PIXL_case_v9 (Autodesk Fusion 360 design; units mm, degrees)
part number: 0.96Oled_W_4_Buttons
base_feature "Base Feature"
work_plane "WorkPlane1" AlongDistance -6.5 ExtraOffset 0
sketch "Sketch1" plane through (0, 0, -6.5) normal (0, 0, 1) x axis (1, 0, 0)
  line L1 (24.2, -27.5) -> (-24.2, -27.5)
  line L2 (24.2, 15.7) -> (24.2, -27.5)
  line L3 (-24.2, 15.7) -> (24.2, 15.7)
  line L4 (-24.2, -27.5) -> (-24.2, 15.7)
extrude "Extrude1" new body sketch "Sketch1" along normal blind 11.8
fillet "Fillet1" radius 5
fillet "Fillet2" radius 1.4
work_plane "WorkPlane2" AlongDistance -6.5 ExtraOffset 0
sketch "Sketch2" plane through (0, 0, -6.5) normal (0, 0, 1) x axis (1, 0, 0)
  line L1 (22.2, -25.5) -> (-22.2, -25.5)
  line L2 (22.2, 13.7) -> (22.2, -25.5)
  line L3 (-22.2, 13.7) -> (22.2, 13.7)
  line L4 (-22.2, -25.5) -> (-22.2, 13.7)
extrude "Extrude2" cut sketch "Sketch2" along normal blind 9.3
fillet "Fillet3" radius 1.7
work_plane "WorkPlane3" AlongDistance 2.79 ExtraOffset 0
sketch "Sketch3" plane through (0, 0, 2.79) normal (0, 0, 1) x axis (1, 0, 0)
  line L1 (20.7, -11.3) -> (11, -11.3)
  line L2 (20.7, 11.7) -> (20.7, -11.3)
  line L3 (11, 11.7) -> (20.7, 11.7)
  line L4 (11, -11.3) -> (11, 11.7)
extrude "Extrude3" cut sketch "Sketch3" along normal blind 1.56
work_plane "WorkPlane4" AlongDistance 2.79 ExtraOffset 0
sketch "Sketch4" plane through (0, 0, 2.79) normal (0, 0, 1) x axis (1, 0, 0)
  line L1 (10, 9.6) -> (-10.8, 9.6)
  line L2 (10, 12.2) -> (10, 9.6)
  line L3 (-10.8, 12.2) -> (10, 12.2)
  line L4 (-10.8, 9.6) -> (-10.8, 12.2)
extrude "Extrude4" cut sketch "Sketch4" along normal blind 0.91
work_plane "WorkPlane5" AlongDistance 4.34 ExtraOffset 0
sketch "Sketch5" plane through (0, 0, 4.34) normal (0, 0, 1) x axis (1, 0, 0)
  line L1 (12.1, 5.6) -> (11.5, 5.6)
  line L2 (12.1, 11.8) -> (12.1, 5.6)
  line L3 (11.5, 11.8) -> (12.1, 11.8)
  line L4 (11.5, 5.6) -> (11.5, 11.8)
extrude "Extrude5" cut sketch "Sketch5" along normal blind 1.06
work_plane "WorkPlane6" AlongDistance 4.34 ExtraOffset 0
sketch "Sketch6" plane through (0, 0, 4.34) normal (0, 0, 1) x axis (1, 0, 0)
  line L1 (19.6, 11.2) -> (11.5, 11.2)
  line L2 (19.6, 11.8) -> (19.6, 11.2)
  line L3 (11.5, 11.8) -> (19.6, 11.8)
  line L4 (11.5, 11.2) -> (11.5, 11.8)
extrude "Extrude6" cut sketch "Sketch6" along normal blind 1.06
work_plane "WorkPlane7" AlongDistance 4.34 ExtraOffset 0
sketch "Sketch7" plane through (0, 0, 4.34) normal (0, 0, 1) x axis (1, 0, 0)
  line L1 (19.6, 5.6) -> (11.5, 5.6)
  line L2 (19.6, 6.2) -> (19.6, 5.6)
  line L3 (11.5, 6.2) -> (19.6, 6.2)
  line L4 (11.5, 5.6) -> (11.5, 6.2)
extrude "Extrude7" cut sketch "Sketch7" along normal blind 1.06
work_plane "WorkPlane8" AlongDistance 4.34 ExtraOffset 0
sketch "Sketch8" plane through (0, 0, 4.34) normal (0, 0, 1) x axis (1, 0, 0)
  line L1 (12.1, -0.07) -> (11.5, -0.07)
  line L2 (12.1, 6.13) -> (12.1, -0.07)
  line L3 (11.5, 6.13) -> (12.1, 6.13)
  line L4 (11.5, -0.07) -> (11.5, 6.13)
extrude "Extrude8" cut sketch "Sketch8" along normal blind 1.06
work_plane "WorkPlane9" AlongDistance 4.34 ExtraOffset 0
sketch "Sketch9" plane through (0, 0, 4.34) normal (0, 0, 1) x axis (1, 0, 0)
  line L1 (19.6, 5.53) -> (11.5, 5.53)
  line L2 (19.6, 6.13) -> (19.6, 5.53)
  line L3 (11.5, 6.13) -> (19.6, 6.13)
  line L4 (11.5, 5.53) -> (11.5, 6.13)
extrude "Extrude9" cut sketch "Sketch9" along normal blind 1.06
work_plane "WorkPlane10" AlongDistance 4.34 ExtraOffset 0
sketch "Sketch10" plane through (0, 0, 4.34) normal (0, 0, 1) x axis (1, 0, 0)
  line L1 (19.6, -0.07) -> (11.5, -0.07)
  line L2 (19.6, 0.53) -> (19.6, -0.07)
  line L3 (11.5, 0.53) -> (19.6, 0.53)
  line L4 (11.5, -0.07) -> (11.5, 0.53)
extrude "Extrude10" cut sketch "Sketch10" along normal blind 1.06
work_plane "WorkPlane11" AlongDistance 4.34 ExtraOffset 0
sketch "Sketch11" plane through (0, 0, 4.34) normal (0, 0, 1) x axis (1, 0, 0)
  line L1 (12.1, -5.73) -> (11.5, -5.73)
  line L2 (12.1, 0.47) -> (12.1, -5.73)
  line L3 (11.5, 0.47) -> (12.1, 0.47)
  line L4 (11.5, -5.73) -> (11.5, 0.47)
extrude "Extrude11" cut sketch "Sketch11" along normal blind 1.06
work_plane "WorkPlane12" AlongDistance 4.34 ExtraOffset 0
sketch "Sketch12" plane through (0, 0, 4.34) normal (0, 0, 1) x axis (1, 0, 0)
  line L1 (19.6, -0.13) -> (11.5, -0.13)
  line L2 (19.6, 0.47) -> (19.6, -0.13)
  line L3 (11.5, 0.47) -> (19.6, 0.47)
  line L4 (11.5, -0.13) -> (11.5, 0.47)
extrude "Extrude12" cut sketch "Sketch12" along normal blind 1.06
work_plane "WorkPlane13" AlongDistance 4.34 ExtraOffset 0
sketch "Sketch13" plane through (0, 0, 4.34) normal (0, 0, 1) x axis (1, 0, 0)
  line L1 (19.6, -5.73) -> (11.5, -5.73)
  line L2 (19.6, -5.13) -> (19.6, -5.73)
  line L3 (11.5, -5.13) -> (19.6, -5.13)
  line L4 (11.5, -5.73) -> (11.5, -5.13)
extrude "Extrude13" cut sketch "Sketch13" along normal blind 1.06
work_plane "WorkPlane14" AlongDistance 4.34 ExtraOffset 0
sketch "Sketch14" plane through (0, 0, 4.34) normal (0, 0, 1) x axis (1, 0, 0)
  line L1 (12.1, -11.4) -> (11.5, -11.4)
  line L2 (12.1, -5.2) -> (12.1, -11.4)
  line L3 (11.5, -5.2) -> (12.1, -5.2)
  line L4 (11.5, -11.4) -> (11.5, -5.2)
extrude "Extrude14" cut sketch "Sketch14" along normal blind 1.06
work_plane "WorkPlane15" AlongDistance 4.34 ExtraOffset 0
sketch "Sketch15" plane through (0, 0, 4.34) normal (0, 0, 1) x axis (1, 0, 0)
  line L1 (19.6, -5.8) -> (11.5, -5.8)
  line L2 (19.6, -5.2) -> (19.6, -5.8)
  line L3 (11.5, -5.2) -> (19.6, -5.2)
  line L4 (11.5, -5.8) -> (11.5, -5.2)
extrude "Extrude15" cut sketch "Sketch15" along normal blind 1.06
work_plane "WorkPlane16" AlongDistance 4.34 ExtraOffset 0
sketch "Sketch16" plane through (0, 0, 4.34) normal (0, 0, 1) x axis (1, 0, 0)
  line L1 (19.6, -11.4) -> (11.5, -11.4)
  line L2 (19.6, -10.8) -> (19.6, -11.4)
  line L3 (11.5, -10.8) -> (19.6, -10.8)
  line L4 (11.5, -11.4) -> (11.5, -10.8)
extrude "Extrude16" cut sketch "Sketch16" along normal blind 1.06
work_plane "WorkPlane17" AlongDistance 4.34 ExtraOffset 0
sketch "Sketch17" plane through (0, 0, 4.34) normal (0, 0, 1) x axis (1, 0, 0)
  line L1 (20.7, 6.2) -> (18.4, 6.2)
  line L2 (20.7, 11.2) -> (20.7, 6.2)
  line L3 (18.4, 11.2) -> (20.7, 11.2)
  line L4 (18.4, 6.2) -> (18.4, 11.2)
extrude "Extrude17" cut sketch "Sketch17" along normal blind 0.46
work_plane "WorkPlane18" AlongDistance 4.34 ExtraOffset 0
sketch "Sketch18" plane through (0, 0, 4.34) normal (0, 0, 1) x axis (1, 0, 0)
  line L1 (20.7, 0.53) -> (18.4, 0.53)
  line L2 (20.7, 5.53) -> (20.7, 0.53)
  line L3 (18.4, 5.53) -> (20.7, 5.53)
  line L4 (18.4, 0.53) -> (18.4, 5.53)
extrude "Extrude18" cut sketch "Sketch18" along normal blind 0.46
work_plane "WorkPlane19" AlongDistance 4.34 ExtraOffset 0
sketch "Sketch19" plane through (0, 0, 4.34) normal (0, 0, 1) x axis (1, 0, 0)
  line L1 (20.7, -5.13) -> (18.4, -5.13)
  line L2 (20.7, -0.13) -> (20.7, -5.13)
  line L3 (18.4, -0.13) -> (20.7, -0.13)
  line L4 (18.4, -5.13) -> (18.4, -0.13)
extrude "Extrude19" cut sketch "Sketch19" along normal blind 0.46
work_plane "WorkPlane20" AlongDistance 4.34 ExtraOffset 0
sketch "Sketch20" plane through (0, 0, 4.34) normal (0, 0, 1) x axis (1, 0, 0)
  line L1 (20.7, -10.8) -> (18.4, -10.8)
  line L2 (20.7, -5.8) -> (20.7, -10.8)
  line L3 (18.4, -5.8) -> (20.7, -5.8)
  line L4 (18.4, -10.8) -> (18.4, -5.8)
extrude "Extrude20" cut sketch "Sketch20" along normal blind 0.46
work_plane "WorkPlane21" AlongDistance 2.79 ExtraOffset 0
sketch "Sketch21" plane through (0, 0, 2.79) normal (0, 0, 1) x axis (1, 0, 0)
  line L1 (7, -6.6) -> (-16.3, -6.6)
  line L2 (7, 6.4) -> (7, -6.6)
  line L3 (-16.3, 6.4) -> (7, 6.4)
  line L4 (-16.3, -6.6) -> (-16.3, 6.4)
extrude "Extrude21" cut sketch "Sketch21" along normal blind 2.61
chamfer "Chamfer1" distance 1.2
work_plane "WorkPlane22" AlongDistance 1.6 ExtraOffset 0
sketch "Sketch22" plane through (0, 0, 1.6) normal (0, 0, 1) x axis (1, 0, 0)
  circle C1 centre (-20.5, -12) radius 1.5
extrude "Extrude22" add sketch "Sketch22" along normal blind 1.21
work_plane "WorkPlane23" AlongDistance 1.6 ExtraOffset 0
sketch "Sketch23" plane through (0, 0, 1.6) normal (0, 0, 1) x axis (1, 0, 0)
  circle C1 centre (-20.5, 12) radius 1.5
extrude "Extrude23" add sketch "Sketch23" along normal blind 1.21
work_plane "WorkPlane24" AlongDistance 1.6 ExtraOffset 0
sketch "Sketch24" plane through (0, 0, 1.6) normal (0, 0, 1) x axis (1, 0, 0)
  circle C1 centre (20.5, -12) radius 1.5
extrude "Extrude24" add sketch "Sketch24" along normal blind 1.21
work_plane "WorkPlane25" AlongDistance 1.6 ExtraOffset 0
sketch "Sketch25" plane through (0, 0, 1.6) normal (0, 0, 1) x axis (1, 0, 0)
  circle C1 centre (20.5, 12) radius 1.5
extrude "Extrude25" add sketch "Sketch25" along normal blind 1.21
work_plane "WorkPlane26" AlongDistance 5.3 ExtraOffset 0
sketch "Sketch26" plane through (0, 0, 5.3) normal (0, 0, 1) x axis (1, 0, 0)
  line L1 (-16.5, -17.8) -> (-19.8, -17.8)
  line L2 (-16.5, -16.7) -> (-16.5, -17.8)
  line L3 (-19.8, -16.7) -> (-16.5, -16.7)
  line L4 (-19.8, -17.8) -> (-19.8, -16.7)
  line L5 (-18.7, -18.9) -> (-19.8, -18.9)
  line L6 (-18.7, -17.8) -> (-18.7, -18.9)
  line L7 (-19.8, -17.8) -> (-18.7, -17.8)
  line L8 (-19.8, -18.9) -> (-19.8, -17.8)
  line L9 (-15.4, -18.9) -> (-16.5, -18.9)
  line L10 (-15.4, -17.8) -> (-15.4, -18.9)
  line L11 (-16.5, -17.8) -> (-15.4, -17.8)
  line L12 (-16.5, -18.9) -> (-16.5, -17.8)
  line L13 (-18.7, -20) -> (-19.8, -20)
  line L14 (-18.7, -18.9) -> (-18.7, -20)
  line L15 (-19.8, -18.9) -> (-18.7, -18.9)
  line L16 (-19.8, -20) -> (-19.8, -18.9)
  line L17 (-15.4, -20) -> (-16.5, -20)
  line L18 (-15.4, -18.9) -> (-15.4, -20)
  line L19 (-16.5, -18.9) -> (-15.4, -18.9)
  line L20 (-16.5, -20) -> (-16.5, -18.9)
  line L21 (-16.5, -21.1) -> (-19.8, -21.1)
  line L22 (-16.5, -20) -> (-16.5, -21.1)
  line L23 (-19.8, -20) -> (-16.5, -20)
  line L24 (-19.8, -21.1) -> (-19.8, -20)
  line L25 (-18.7, -22.2) -> (-19.8, -22.2)
  line L26 (-18.7, -21.1) -> (-18.7, -22.2)
  line L27 (-19.8, -21.1) -> (-18.7, -21.1)
  line L28 (-19.8, -22.2) -> (-19.8, -21.1)
  line L29 (-18.7, -23.3) -> (-19.8, -23.3)
  line L30 (-18.7, -22.2) -> (-18.7, -23.3)
  line L31 (-19.8, -22.2) -> (-18.7, -22.2)
  line L32 (-19.8, -23.3) -> (-19.8, -22.2)
  line L33 (-13.2, -17.8) -> (-14.3, -17.8)
  line L34 (-13.2, -16.7) -> (-13.2, -17.8)
  line L35 (-14.3, -16.7) -> (-13.2, -16.7)
  line L36 (-14.3, -17.8) -> (-14.3, -16.7)
  line L37 (-13.2, -20) -> (-14.3, -20)
  line L38 (-13.2, -18.9) -> (-13.2, -20)
  line L39 (-14.3, -18.9) -> (-13.2, -18.9)
  line L40 (-14.3, -20) -> (-14.3, -18.9)
  line L41 (-13.2, -21.1) -> (-14.3, -21.1)
  line L42 (-13.2, -20) -> (-13.2, -21.1)
  line L43 (-14.3, -20) -> (-13.2, -20)
  line L44 (-14.3, -21.1) -> (-14.3, -20)
  line L45 (-13.2, -22.2) -> (-14.3, -22.2)
  line L46 (-13.2, -21.1) -> (-13.2, -22.2)
  line L47 (-14.3, -21.1) -> (-13.2, -21.1)
  line L48 (-14.3, -22.2) -> (-14.3, -21.1)
  line L49 (-13.2, -23.3) -> (-14.3, -23.3)
  line L50 (-13.2, -22.2) -> (-13.2, -23.3)
  line L51 (-14.3, -22.2) -> (-13.2, -22.2)
  line L52 (-14.3, -23.3) -> (-14.3, -22.2)
  line L53 (-11, -17.8) -> (-12.1, -17.8)
  line L54 (-11, -16.7) -> (-11, -17.8)
  line L55 (-12.1, -16.7) -> (-11, -16.7)
  line L56 (-12.1, -17.8) -> (-12.1, -16.7)
  line L57 (-7.7, -17.8) -> (-8.8, -17.8)
  line L58 (-7.7, -16.7) -> (-7.7, -17.8)
  line L59 (-8.8, -16.7) -> (-7.7, -16.7)
  line L60 (-8.8, -17.8) -> (-8.8, -16.7)
  line L61 (-11, -18.9) -> (-12.1, -18.9)
  line L62 (-11, -17.8) -> (-11, -18.9)
  line L63 (-12.1, -17.8) -> (-11, -17.8)
  line L64 (-12.1, -18.9) -> (-12.1, -17.8)
  line L65 (-7.7, -18.9) -> (-8.8, -18.9)
  line L66 (-7.7, -17.8) -> (-7.7, -18.9)
  line L67 (-8.8, -17.8) -> (-7.7, -17.8)
  line L68 (-8.8, -18.9) -> (-8.8, -17.8)
  line L69 (-8.8, -20) -> (-11, -20)
  line L70 (-8.8, -18.9) -> (-8.8, -20)
  line L71 (-11, -18.9) -> (-8.8, -18.9)
  line L72 (-11, -20) -> (-11, -18.9)
  line L73 (-8.8, -21.1) -> (-11, -21.1)
  line L74 (-8.8, -20) -> (-8.8, -21.1)
  line L75 (-11, -20) -> (-8.8, -20)
  line L76 (-11, -21.1) -> (-11, -20)
  line L77 (-11, -22.2) -> (-12.1, -22.2)
  line L78 (-11, -21.1) -> (-11, -22.2)
  line L79 (-12.1, -21.1) -> (-11, -21.1)
  line L80 (-12.1, -22.2) -> (-12.1, -21.1)
  line L81 (-7.7, -22.2) -> (-8.8, -22.2)
  line L82 (-7.7, -21.1) -> (-7.7, -22.2)
  line L83 (-8.8, -21.1) -> (-7.7, -21.1)
  line L84 (-8.8, -22.2) -> (-8.8, -21.1)
  line L85 (-11, -23.3) -> (-12.1, -23.3)
  line L86 (-11, -22.2) -> (-11, -23.3)
  line L87 (-12.1, -22.2) -> (-11, -22.2)
  line L88 (-12.1, -23.3) -> (-12.1, -22.2)
  line L89 (-7.7, -23.3) -> (-8.8, -23.3)
  line L90 (-7.7, -22.2) -> (-7.7, -23.3)
  line L91 (-8.8, -22.2) -> (-7.7, -22.2)
  line L92 (-8.8, -23.3) -> (-8.8, -22.2)
  line L93 (-5.5, -17.8) -> (-6.6, -17.8)
  line L94 (-5.5, -16.7) -> (-5.5, -17.8)
  line L95 (-6.6, -16.7) -> (-5.5, -16.7)
  line L96 (-6.6, -17.8) -> (-6.6, -16.7)
  line L97 (-5.5, -18.9) -> (-6.6, -18.9)
  line L98 (-5.5, -17.8) -> (-5.5, -18.9)
  line L99 (-6.6, -17.8) -> (-5.5, -17.8)
  line L100 (-6.6, -18.9) -> (-6.6, -17.8)
  line L101 (-5.5, -20) -> (-6.6, -20)
  line L102 (-5.5, -18.9) -> (-5.5, -20)
  line L103 (-6.6, -18.9) -> (-5.5, -18.9)
  line L104 (-6.6, -20) -> (-6.6, -18.9)
  line L105 (-5.5, -21.1) -> (-6.6, -21.1)
  line L106 (-5.5, -20) -> (-5.5, -21.1)
  line L107 (-6.6, -20) -> (-5.5, -20)
  line L108 (-6.6, -21.1) -> (-6.6, -20)
  line L109 (-5.5, -22.2) -> (-6.6, -22.2)
  line L110 (-5.5, -21.1) -> (-5.5, -22.2)
  line L111 (-6.6, -21.1) -> (-5.5, -21.1)
  line L112 (-6.6, -22.2) -> (-6.6, -21.1)
  line L113 (-2.2, -23.3) -> (-6.6, -23.3)
  line L114 (-2.2, -22.2) -> (-2.2, -23.3)
  line L115 (-6.6, -22.2) -> (-2.2, -22.2)
  line L116 (-6.6, -23.3) -> (-6.6, -22.2)
extrude "Extrude26" cut sketch "Sketch26" against normal blind 0.4
work_plane "WorkPlane27" AlongDistance 5.3 ExtraOffset 0
sketch "Sketch27" plane through (0, 0, 5.3) normal (0, 0, 1) x axis (1, 0, 0)
  line L1 (3.25, -22.25) -> (2.5, -22.25)
  line L2 (3.25, -21.5) -> (3.25, -22.25)
  line L3 (2.5, -21.5) -> (3.25, -21.5)
  line L4 (2.5, -22.25) -> (2.5, -21.5)
  line L5 (4.5, -22.25) -> (3.75, -22.25)
  line L6 (4.5, -21.5) -> (4.5, -22.25)
  line L7 (3.75, -21.5) -> (4.5, -21.5)
  line L8 (3.75, -22.25) -> (3.75, -21.5)
  line L9 (5.75, -22.25) -> (5, -22.25)
  line L10 (5.75, -21.5) -> (5.75, -22.25)
  line L11 (5, -21.5) -> (5.75, -21.5)
  line L12 (5, -22.25) -> (5, -21.5)
  line L13 (7, -22.25) -> (6.25, -22.25)
  line L14 (7, -21.5) -> (7, -22.25)
  line L15 (6.25, -21.5) -> (7, -21.5)
  line L16 (6.25, -22.25) -> (6.25, -21.5)
  line L17 (8.25, -22.25) -> (7.5, -22.25)
  line L18 (8.25, -21.5) -> (8.25, -22.25)
  line L19 (7.5, -21.5) -> (8.25, -21.5)
  line L20 (7.5, -22.25) -> (7.5, -21.5)
  line L21 (9.5, -22.25) -> (8.75, -22.25)
  line L22 (9.5, -21.5) -> (9.5, -22.25)
  line L23 (8.75, -21.5) -> (9.5, -21.5)
  line L24 (8.75, -22.25) -> (8.75, -21.5)
  line L25 (10.75, -22.25) -> (10, -22.25)
  line L26 (10.75, -21.5) -> (10.75, -22.25)
  line L27 (10, -21.5) -> (10.75, -21.5)
  line L28 (10, -22.25) -> (10, -21.5)
  line L29 (13.25, -22.25) -> (12.5, -22.25)
  line L30 (13.25, -21.5) -> (13.25, -22.25)
  line L31 (12.5, -21.5) -> (13.25, -21.5)
  line L32 (12.5, -22.25) -> (12.5, -21.5)
  line L33 (15.75, -22.25) -> (15, -22.25)
  line L34 (15.75, -21.5) -> (15.75, -22.25)
  line L35 (15, -21.5) -> (15.75, -21.5)
  line L36 (15, -22.25) -> (15, -21.5)
  line L37 (3.25, -21) -> (2.5, -21)
  line L38 (3.25, -20.25) -> (3.25, -21)
  line L39 (2.5, -20.25) -> (3.25, -20.25)
  line L40 (2.5, -21) -> (2.5, -20.25)
  line L41 (4.5, -21) -> (3.75, -21)
  line L42 (4.5, -20.25) -> (4.5, -21)
  line L43 (3.75, -20.25) -> (4.5, -20.25)
  line L44 (3.75, -21) -> (3.75, -20.25)
  line L45 (7, -21) -> (6.25, -21)
  line L46 (7, -20.25) -> (7, -21)
  line L47 (6.25, -20.25) -> (7, -20.25)
  line L48 (6.25, -21) -> (6.25, -20.25)
  line L49 (9.5, -21) -> (8.75, -21)
  line L50 (9.5, -20.25) -> (9.5, -21)
  line L51 (8.75, -20.25) -> (9.5, -20.25)
  line L52 (8.75, -21) -> (8.75, -20.25)
  line L53 (12, -21) -> (11.25, -21)
  line L54 (12, -20.25) -> (12, -21)
  line L55 (11.25, -20.25) -> (12, -20.25)
  line L56 (11.25, -21) -> (11.25, -20.25)
  line L57 (3.25, -19.75) -> (2.5, -19.75)
  line L58 (3.25, -19) -> (3.25, -19.75)
  line L59 (2.5, -19) -> (3.25, -19)
  line L60 (2.5, -19.75) -> (2.5, -19)
  line L61 (4.5, -19.75) -> (3.75, -19.75)
  line L62 (4.5, -19) -> (4.5, -19.75)
  line L63 (3.75, -19) -> (4.5, -19)
  line L64 (3.75, -19.75) -> (3.75, -19)
  line L65 (5.75, -19.75) -> (5, -19.75)
  line L66 (5.75, -19) -> (5.75, -19.75)
  line L67 (5, -19) -> (5.75, -19)
  line L68 (5, -19.75) -> (5, -19)
  line L69 (7, -19.75) -> (6.25, -19.75)
  line L70 (7, -19) -> (7, -19.75)
  line L71 (6.25, -19) -> (7, -19)
  line L72 (6.25, -19.75) -> (6.25, -19)
  line L73 (8.25, -19.75) -> (7.5, -19.75)
  line L74 (8.25, -19) -> (8.25, -19.75)
  line L75 (7.5, -19) -> (8.25, -19)
  line L76 (7.5, -19.75) -> (7.5, -19)
  line L77 (10.75, -19.75) -> (10, -19.75)
  line L78 (10.75, -19) -> (10.75, -19.75)
  line L79 (10, -19) -> (10.75, -19)
  line L80 (10, -19.75) -> (10, -19)
  line L81 (13.25, -19.75) -> (12.5, -19.75)
  line L82 (13.25, -19) -> (13.25, -19.75)
  line L83 (12.5, -19) -> (13.25, -19)
  line L84 (12.5, -19.75) -> (12.5, -19)
  line L85 (15.75, -19.75) -> (15, -19.75)
  line L86 (15.75, -19) -> (15.75, -19.75)
  line L87 (15, -19) -> (15.75, -19)
  line L88 (15, -19.75) -> (15, -19)
  line L89 (3.25, -18.5) -> (2.5, -18.5)
  line L90 (3.25, -17.75) -> (3.25, -18.5)
  line L91 (2.5, -17.75) -> (3.25, -17.75)
  line L92 (2.5, -18.5) -> (2.5, -17.75)
  line L93 (4.5, -18.5) -> (3.75, -18.5)
  line L94 (4.5, -17.75) -> (4.5, -18.5)
  line L95 (3.75, -17.75) -> (4.5, -17.75)
  line L96 (3.75, -18.5) -> (3.75, -17.75)
  line L97 (7, -18.5) -> (6.25, -18.5)
  line L98 (7, -17.75) -> (7, -18.5)
  line L99 (6.25, -17.75) -> (7, -17.75)
  line L100 (6.25, -18.5) -> (6.25, -17.75)
  line L101 (9.5, -18.5) -> (8.75, -18.5)
  line L102 (9.5, -17.75) -> (9.5, -18.5)
  line L103 (8.75, -17.75) -> (9.5, -17.75)
  line L104 (8.75, -18.5) -> (8.75, -17.75)
  line L105 (12, -18.5) -> (11.25, -18.5)
  line L106 (12, -17.75) -> (12, -18.5)
  line L107 (11.25, -17.75) -> (12, -17.75)
  line L108 (11.25, -18.5) -> (11.25, -17.75)
extrude "Extrude27" cut sketch "Sketch27" against normal blind 0.35
work_plane "WorkPlane28" AlongDistance 5.3 ExtraOffset 0
sketch "Sketch28" plane through (0, 0, 5.3) normal (0, 0, 1) x axis (1, 0, 0)
  line L1 (17.125, 9.375) -> (16.675, 9.375)
  line L2 (17.125, 9.825) -> (17.125, 9.375)
  line L3 (16.675, 9.825) -> (17.125, 9.825)
  line L4 (16.675, 9.375) -> (16.675, 9.825)
  line L5 (17.575, 8.925) -> (16.225, 8.925)
  line L6 (17.575, 9.375) -> (17.575, 8.925)
  line L7 (16.225, 9.375) -> (17.575, 9.375)
  line L8 (16.225, 8.925) -> (16.225, 9.375)
  line L9 (16.675, 8.475) -> (15.775, 8.475)
  line L10 (16.675, 8.925) -> (16.675, 8.475)
  line L11 (15.775, 8.925) -> (16.675, 8.925)
  line L12 (15.775, 8.475) -> (15.775, 8.925)
  line L13 (18.025, 8.475) -> (17.125, 8.475)
  line L14 (18.025, 8.925) -> (18.025, 8.475)
  line L15 (17.125, 8.925) -> (18.025, 8.925)
  line L16 (17.125, 8.475) -> (17.125, 8.925)
  line L17 (16.225, 8.025) -> (15.325, 8.025)
  line L18 (16.225, 8.475) -> (16.225, 8.025)
  line L19 (15.325, 8.475) -> (16.225, 8.475)
  line L20 (15.325, 8.025) -> (15.325, 8.475)
  line L21 (18.475, 8.025) -> (17.575, 8.025)
  line L22 (18.475, 8.475) -> (18.475, 8.025)
  line L23 (17.575, 8.475) -> (18.475, 8.475)
  line L24 (17.575, 8.025) -> (17.575, 8.475)
  line L25 (15.775, 7.575) -> (15.325, 7.575)
  line L26 (15.775, 8.025) -> (15.775, 7.575)
  line L27 (15.325, 8.025) -> (15.775, 8.025)
  line L28 (15.325, 7.575) -> (15.325, 8.025)
  line L29 (18.475, 7.575) -> (18.025, 7.575)
  line L30 (18.475, 8.025) -> (18.475, 7.575)
  line L31 (18.025, 8.025) -> (18.475, 8.025)
  line L32 (18.025, 7.575) -> (18.025, 8.025)
  line L33 (15.775, 3.705) -> (15.325, 3.705)
  line L34 (15.775, 4.155) -> (15.775, 3.705)
  line L35 (15.325, 4.155) -> (15.775, 4.155)
  line L36 (15.325, 3.705) -> (15.325, 4.155)
  line L37 (18.475, 3.705) -> (18.025, 3.705)
  line L38 (18.475, 4.155) -> (18.475, 3.705)
  line L39 (18.025, 4.155) -> (18.475, 4.155)
  line L40 (18.025, 3.705) -> (18.025, 4.155)
  line L41 (16.225, 3.255) -> (15.325, 3.255)
  line L42 (16.225, 3.705) -> (16.225, 3.255)
  line L43 (15.325, 3.705) -> (16.225, 3.705)
  line L44 (15.325, 3.255) -> (15.325, 3.705)
  line L45 (18.475, 3.255) -> (17.575, 3.255)
  line L46 (18.475, 3.705) -> (18.475, 3.255)
  line L47 (17.575, 3.705) -> (18.475, 3.705)
  line L48 (17.575, 3.255) -> (17.575, 3.705)
  line L49 (16.675, 2.805) -> (15.775, 2.805)
  line L50 (16.675, 3.255) -> (16.675, 2.805)
  line L51 (15.775, 3.255) -> (16.675, 3.255)
  line L52 (15.775, 2.805) -> (15.775, 3.255)
  line L53 (18.025, 2.805) -> (17.125, 2.805)
  line L54 (18.025, 3.255) -> (18.025, 2.805)
  line L55 (17.125, 3.255) -> (18.025, 3.255)
  line L56 (17.125, 2.805) -> (17.125, 3.255)
  line L57 (17.575, 2.355) -> (16.225, 2.355)
  line L58 (17.575, 2.805) -> (17.575, 2.355)
  line L59 (16.225, 2.805) -> (17.575, 2.805)
  line L60 (16.225, 2.355) -> (16.225, 2.805)
  line L61 (17.125, 1.905) -> (16.675, 1.905)
  line L62 (17.125, 2.355) -> (17.125, 1.905)
  line L63 (16.675, 2.355) -> (17.125, 2.355)
  line L64 (16.675, 1.905) -> (16.675, 2.355)
  line L65 (18.475, -1.955) -> (15.325, -1.955)
  line L66 (18.475, -1.505) -> (18.475, -1.955)
  line L67 (15.325, -1.505) -> (18.475, -1.505)
  line L68 (15.325, -1.955) -> (15.325, -1.505)
  line L69 (18.475, -2.855) -> (15.325, -2.855)
  line L70 (18.475, -2.405) -> (18.475, -2.855)
  line L71 (15.325, -2.405) -> (18.475, -2.405)
  line L72 (15.325, -2.855) -> (15.325, -2.405)
  line L73 (18.475, -3.755) -> (15.325, -3.755)
  line L74 (18.475, -3.305) -> (18.475, -3.755)
  line L75 (15.325, -3.305) -> (18.475, -3.305)
  line L76 (15.325, -3.755) -> (15.325, -3.305)
  line L77 (16.675, -7.175) -> (16.225, -7.175)
  line L78 (16.675, -6.725) -> (16.675, -7.175)
  line L79 (16.225, -6.725) -> (16.675, -6.725)
  line L80 (16.225, -7.175) -> (16.225, -6.725)
  line L81 (16.675, -7.625) -> (15.775, -7.625)
  line L82 (16.675, -7.175) -> (16.675, -7.625)
  line L83 (15.775, -7.175) -> (16.675, -7.175)
  line L84 (15.775, -7.625) -> (15.775, -7.175)
  line L85 (18.025, -8.075) -> (15.325, -8.075)
  line L86 (18.025, -7.625) -> (18.025, -8.075)
  line L87 (15.325, -7.625) -> (18.025, -7.625)
  line L88 (15.325, -8.075) -> (15.325, -7.625)
  line L89 (16.675, -8.525) -> (15.775, -8.525)
  line L90 (16.675, -8.075) -> (16.675, -8.525)
  line L91 (15.775, -8.075) -> (16.675, -8.075)
  line L92 (15.775, -8.525) -> (15.775, -8.075)
  line L93 (18.475, -8.525) -> (18.025, -8.525)
  line L94 (18.475, -8.075) -> (18.475, -8.525)
  line L95 (18.025, -8.075) -> (18.475, -8.075)
  line L96 (18.025, -8.525) -> (18.025, -8.075)
  line L97 (16.675, -8.975) -> (16.225, -8.975)
  line L98 (16.675, -8.525) -> (16.675, -8.975)
  line L99 (16.225, -8.525) -> (16.675, -8.525)
  line L100 (16.225, -8.975) -> (16.225, -8.525)
  line L101 (18.475, -8.975) -> (18.025, -8.975)
  line L102 (18.475, -8.525) -> (18.475, -8.975)
  line L103 (18.025, -8.525) -> (18.475, -8.525)
  line L104 (18.025, -8.975) -> (18.025, -8.525)
  line L105 (18.475, -9.425) -> (18.025, -9.425)
  line L106 (18.475, -8.975) -> (18.475, -9.425)
  line L107 (18.025, -8.975) -> (18.475, -8.975)
  line L108 (18.025, -9.425) -> (18.025, -8.975)
  line L109 (18.025, -9.875) -> (15.775, -9.875)
  line L110 (18.025, -9.425) -> (18.025, -9.875)
  line L111 (15.775, -9.425) -> (18.025, -9.425)
  line L112 (15.775, -9.875) -> (15.775, -9.425)
extrude "Extrude28" cut sketch "Sketch28" against normal blind 0.3
work_plane "WorkPlane29" AlongDistance -4.9 ExtraOffset 0
sketch "Sketch29" plane through (0, 0, -4.9) normal (0, 0, 1) x axis (1, 0, 0)
  line L1 (24.7, -21) -> (21.7, -21)
  line L2 (24.7, -11) -> (24.7, -21)
  line L3 (21.7, -11) -> (24.7, -11)
  line L4 (21.7, -21) -> (21.7, -11)
extrude "Extrude29" cut sketch "Sketch29" along normal blind 4
work_plane "WorkPlane30" AlongDistance -5.9 ExtraOffset 0
sketch "Sketch30" plane through (0, 0, -5.9) normal (0, 0, 1) x axis (1, 0, 0)
  line L1 (24.7, -22.5) -> (23.2, -22.5)
  line L2 (24.7, -9.5) -> (24.7, -22.5)
  line L3 (23.2, -9.5) -> (24.7, -9.5)
  line L4 (23.2, -22.5) -> (23.2, -9.5)
extrude "Extrude30" cut sketch "Sketch30" along normal blind 6
work_plane "WorkPlane31" AlongDistance -3.2 ExtraOffset 0
sketch "Sketch31" plane through (0, 0, -3.2) normal (0, 0, 1) x axis (1, 0, 0)
  line L1 (-22.2, -20.4) -> (-22.81, -20.4)
  line L2 (-22.2, -13.6) -> (-22.2, -20.4)
  line L3 (-22.81, -13.6) -> (-22.2, -13.6)
  line L4 (-22.81, -20.4) -> (-22.81, -13.6)
extrude "Extrude31" cut sketch "Sketch31" along normal blind 2
work_plane "WorkPlane32" AlongDistance -3.2 ExtraOffset 0
sketch "Sketch32" plane through (0, 0, -3.2) normal (0, 0, 1) x axis (1, 0, 0)
  line L1 (22.81, -7.2) -> (22.2, -7.2)
  line L2 (22.81, -0.8) -> (22.81, -7.2)
  line L3 (22.2, -0.8) -> (22.81, -0.8)
  line L4 (22.2, -7.2) -> (22.2, -0.8)
extrude "Extrude32" cut sketch "Sketch32" along normal blind 2
work_plane "WorkPlane33" AlongDistance -6 ExtraOffset 0
sketch "Sketch33" plane through (0, 0, -6) normal (0, 0, 1) x axis (1, 0, 0)
  line L1 (19.4, 13.6) -> (10.6, 13.6)
  line L2 (19.4, 14.6) -> (19.4, 13.6)
  line L3 (10.6, 14.6) -> (19.4, 14.6)
  line L4 (10.6, 13.6) -> (10.6, 14.6)
extrude "Extrude33" cut sketch "Sketch33" along normal blind 1.2
work_plane "WorkPlane34" AlongDistance -6.5 ExtraOffset 0
sketch "Sketch34" plane through (0, 0, -6.5) normal (0, 0, 1) x axis (1, 0, 0)
  line L1 (-10.2, -32.1) -> (-12.6, -32.1)
  line L2 (-10.2, -26.5) -> (-10.2, -32.1)
  line L3 (-12.6, -26.5) -> (-10.2, -26.5)
  line L4 (-12.6, -32.1) -> (-12.6, -26.5)
extrude "Extrude34" add sketch "Sketch34" along normal blind 3
work_plane "WorkPlane35" AlongDistance -7.7 ExtraOffset 0
sketch "Sketch35" plane through (0, 0, -7.7) normal (0, 0, 1) x axis (1, 0, 0)
  line L1 (-10.2, -32.1) -> (-12.6, -32.1)
  line L2 (-10.2, -27.7) -> (-10.2, -32.1)
  line L3 (-12.6, -27.7) -> (-10.2, -27.7)
  line L4 (-12.6, -32.1) -> (-12.6, -27.7)
extrude "Extrude35" add sketch "Sketch35" along normal blind 1.21
work_plane "WorkPlane36" AlongDistance -6.5 ExtraOffset 0
sketch "Sketch36" plane through (0, 0, -6.5) normal (0, 0, 1) x axis (1, 0, 0)
  line L1 (-10.2, 14.7) -> (-12.6, 14.7)
  line L2 (-10.2, 20.3) -> (-10.2, 14.7)
  line L3 (-12.6, 20.3) -> (-10.2, 20.3)
  line L4 (-12.6, 14.7) -> (-12.6, 20.3)
extrude "Extrude36" add sketch "Sketch36" along normal blind 3
work_plane "WorkPlane37" AlongDistance -7.7 ExtraOffset 0
sketch "Sketch37" plane through (0, 0, -7.7) normal (0, 0, 1) x axis (1, 0, 0)
  line L1 (-10.2, 15.9) -> (-12.6, 15.9)
  line L2 (-10.2, 20.3) -> (-10.2, 15.9)
  line L3 (-12.6, 20.3) -> (-10.2, 20.3)
  line L4 (-12.6, 15.9) -> (-12.6, 20.3)
extrude "Extrude37" add sketch "Sketch37" along normal blind 1.21
work_plane "WorkPlane38" AlongDistance -6.5 ExtraOffset 0
sketch "Sketch38" plane through (0, 0, -6.5) normal (0, 0, 1) x axis (1, 0, 0)
  line L1 (12.6, -32.1) -> (10.2, -32.1)
  line L2 (12.6, -26.5) -> (12.6, -32.1)
  line L3 (10.2, -26.5) -> (12.6, -26.5)
  line L4 (10.2, -32.1) -> (10.2, -26.5)
extrude "Extrude38" add sketch "Sketch38" along normal blind 3
work_plane "WorkPlane39" AlongDistance -7.7 ExtraOffset 0
sketch "Sketch39" plane through (0, 0, -7.7) normal (0, 0, 1) x axis (1, 0, 0)
  line L1 (12.6, -32.1) -> (10.2, -32.1)
  line L2 (12.6, -27.7) -> (12.6, -32.1)
  line L3 (10.2, -27.7) -> (12.6, -27.7)
  line L4 (10.2, -32.1) -> (10.2, -27.7)
extrude "Extrude39" add sketch "Sketch39" along normal blind 1.21
work_plane "WorkPlane40" AlongDistance -6.5 ExtraOffset 0
sketch "Sketch40" plane through (0, 0, -6.5) normal (0, 0, 1) x axis (1, 0, 0)
  line L1 (12.6, 14.7) -> (10.2, 14.7)
  line L2 (12.6, 20.3) -> (12.6, 14.7)
  line L3 (10.2, 20.3) -> (12.6, 20.3)
  line L4 (10.2, 14.7) -> (10.2, 20.3)
extrude "Extrude40" add sketch "Sketch40" along normal blind 3
work_plane "WorkPlane41" AlongDistance -7.7 ExtraOffset 0
sketch "Sketch41" plane through (0, 0, -7.7) normal (0, 0, 1) x axis (1, 0, 0)
  line L1 (12.6, 15.9) -> (10.2, 15.9)
  line L2 (12.6, 20.3) -> (12.6, 15.9)
  line L3 (10.2, 20.3) -> (12.6, 20.3)
  line L4 (10.2, 15.9) -> (10.2, 20.3)
extrude "Extrude41" add sketch "Sketch41" along normal blind 1.21
fillet "Fillet4" radius 1.2
sketch "Sketch42" plane through (0, 0, 0) normal (1, 0, 0) x axis (0, 0, -1)
  circle C1 centre (6.2, -30.3) radius 0.55
extrude "Extrude42" cut sketch "Sketch42" distance 13.6
sketch "Sketch43" plane through (0, 0, 0) normal (1, 0, 0) x axis (0, 0, -1)
  circle C1 centre (6.2, 18.5) radius 0.55
extrude "Extrude43" cut sketch "Sketch43" distance 13.6
work_plane "WorkPlane1" AlongDistance -7.7 ExtraOffset 0
sketch "Sketch1" plane through (0, 0, -7.7) normal (0, 0, 1) x axis (1, 0, 0)
  line L1 (24.2, -27.5) -> (-24.2, -27.5)
  line L2 (24.2, 15.7) -> (24.2, -27.5)
  line L3 (-24.2, 15.7) -> (24.2, 15.7)
  line L4 (-24.2, -27.5) -> (-24.2, 15.7)
extrude "Extrude1" new body sketch "Sketch1" along normal blind 1.2
fillet "Fillet1" radius 5
fillet "Fillet2" radius 0.6
work_plane "WorkPlane2" AlongDistance -6.51 ExtraOffset 0
sketch "Sketch2" plane through (0, 0, -6.51) normal (0, 0, 1) x axis (1, 0, 0)
  line L1 (21.95, -0.5) -> (20.95, -0.5)
  line L2 (21.95, 4) -> (21.95, -0.5)
  line L3 (20.95, 4) -> (21.95, 4)
  line L4 (20.95, -0.5) -> (20.95, 4)
extrude "Extrude2" add sketch "Sketch2" along normal blind 1.01
work_plane "WorkPlane3" AlongDistance -6.51 ExtraOffset 0
sketch "Sketch3" plane through (0, 0, -6.51) normal (0, 0, 1) x axis (1, 0, 0)
  line L1 (19, 12.6) -> (11, 12.6)
  line L2 (19, 13.55) -> (19, 12.6)
  line L3 (11, 13.55) -> (19, 13.55)
  line L4 (11, 12.6) -> (11, 13.55)
extrude "Extrude3" add sketch "Sketch3" along normal blind 1.61
work_plane "WorkPlane4" AlongDistance -5.8 ExtraOffset 0
sketch "Sketch4" plane through (0, 0, -5.8) normal (0, 0, 1) x axis (1, 0, 0)
  line L1 (19, 13.5) -> (11, 13.5)
  line L2 (19, 14.35) -> (19, 13.5)
  line L3 (11, 14.35) -> (19, 14.35)
  line L4 (11, 13.5) -> (11, 14.35)
extrude "Extrude4" add sketch "Sketch4" along normal blind 0.75
work_plane "WorkPlane5" AlongDistance -6.51 ExtraOffset 0
sketch "Sketch5" plane through (0, 0, -6.51) normal (0, 0, 1) x axis (1, 0, 0)
  line L1 (-21.25, -20) -> (-22.15, -20)
  line L2 (-21.25, -14) -> (-21.25, -20)
  line L3 (-22.15, -14) -> (-21.25, -14)
  line L4 (-22.15, -20) -> (-22.15, -14)
extrude "Extrude5" add sketch "Sketch5" along normal blind 5.41
work_plane "WorkPlane6" AlongDistance -3.1 ExtraOffset 0
sketch "Sketch6" plane through (0, 0, -3.1) normal (0, 0, 1) x axis (1, 0, 0)
  line L1 (-22.14, -19.7) -> (-22.4, -19.7)
  line L2 (-22.14, -14.3) -> (-22.14, -19.7)
  line L3 (-22.4, -14.3) -> (-22.14, -14.3)
  line L4 (-22.4, -19.7) -> (-22.4, -14.3)
extrude "Extrude6" add sketch "Sketch6" along normal blind 0.2
work_plane "WorkPlane7" AlongDistance -2.9 ExtraOffset 0
sketch "Sketch7" plane through (0, 0, -2.9) normal (0, 0, 1) x axis (1, 0, 0)
  line L1 (-22.14, -19.7) -> (-22.65, -19.7)
  line L2 (-22.14, -14.3) -> (-22.14, -19.7)
  line L3 (-22.65, -14.3) -> (-22.14, -14.3)
  line L4 (-22.65, -19.7) -> (-22.65, -14.3)
extrude "Extrude7" add sketch "Sketch7" along normal blind 0.5
work_plane "WorkPlane8" AlongDistance -2.4 ExtraOffset 0
sketch "Sketch8" plane through (0, 0, -2.4) normal (0, 0, 1) x axis (1, 0, 0)
  line L1 (-22.14, -19.7) -> (-22.48, -19.7)
  line L2 (-22.14, -14.3) -> (-22.14, -19.7)
  line L3 (-22.48, -14.3) -> (-22.14, -14.3)
  line L4 (-22.48, -19.7) -> (-22.48, -14.3)
extrude "Extrude8" add sketch "Sketch8" along normal blind 0.5
work_plane "WorkPlane9" AlongDistance -1.9 ExtraOffset 0
sketch "Sketch9" plane through (0, 0, -1.9) normal (0, 0, 1) x axis (1, 0, 0)
  line L1 (-22.14, -19.7) -> (-22.32, -19.7)
  line L2 (-22.14, -14.3) -> (-22.14, -19.7)
  line L3 (-22.32, -14.3) -> (-22.14, -14.3)
  line L4 (-22.32, -19.7) -> (-22.32, -14.3)
extrude "Extrude9" add sketch "Sketch9" along normal blind 0.5
work_plane "WorkPlane10" AlongDistance -6.51 ExtraOffset 0
sketch "Sketch10" plane through (0, 0, -6.51) normal (0, 0, 1) x axis (1, 0, 0)
  line L1 (22.15, -6.8) -> (21.25, -6.8)
  line L2 (22.15, -1.2) -> (22.15, -6.8)
  line L3 (21.25, -1.2) -> (22.15, -1.2)
  line L4 (21.25, -6.8) -> (21.25, -1.2)
extrude "Extrude10" add sketch "Sketch10" along normal blind 5.41
work_plane "WorkPlane11" AlongDistance -3.1 ExtraOffset 0
sketch "Sketch11" plane through (0, 0, -3.1) normal (0, 0, 1) x axis (1, 0, 0)
  line L1 (22.4, -6.5) -> (22.14, -6.5)
  line L2 (22.4, -1.5) -> (22.4, -6.5)
  line L3 (22.14, -1.5) -> (22.4, -1.5)
  line L4 (22.14, -6.5) -> (22.14, -1.5)
extrude "Extrude11" add sketch "Sketch11" along normal blind 0.2
work_plane "WorkPlane12" AlongDistance -2.9 ExtraOffset 0
sketch "Sketch12" plane through (0, 0, -2.9) normal (0, 0, 1) x axis (1, 0, 0)
  line L1 (22.65, -6.5) -> (22.14, -6.5)
  line L2 (22.65, -1.5) -> (22.65, -6.5)
  line L3 (22.14, -1.5) -> (22.65, -1.5)
  line L4 (22.14, -6.5) -> (22.14, -1.5)
extrude "Extrude12" add sketch "Sketch12" along normal blind 0.5
work_plane "WorkPlane13" AlongDistance -2.4 ExtraOffset 0
sketch "Sketch13" plane through (0, 0, -2.4) normal (0, 0, 1) x axis (1, 0, 0)
  line L1 (22.48, -6.5) -> (22.14, -6.5)
  line L2 (22.48, -1.5) -> (22.48, -6.5)
  line L3 (22.14, -1.5) -> (22.48, -1.5)
  line L4 (22.14, -6.5) -> (22.14, -1.5)
extrude "Extrude13" add sketch "Sketch13" along normal blind 0.5
work_plane "WorkPlane14" AlongDistance -1.9 ExtraOffset 0
sketch "Sketch14" plane through (0, 0, -1.9) normal (0, 0, 1) x axis (1, 0, 0)
  line L1 (22.32, -6.5) -> (22.14, -6.5)
  line L2 (22.32, -1.5) -> (22.32, -6.5)
  line L3 (22.14, -1.5) -> (22.32, -1.5)
  line L4 (22.14, -6.5) -> (22.14, -1.5)
extrude "Extrude14" add sketch "Sketch14" along normal blind 0.5
work_plane "WorkPlane15" AlongDistance -6.51 ExtraOffset 0
sketch "Sketch15" plane through (0, 0, -6.51) normal (0, 0, 1) x axis (1, 0, 0)
  circle C1 centre (20.6, 11.6) radius 0.8
extrude "Extrude15" add sketch "Sketch15" along normal blind 6.46
work_plane "WorkPlane16" AlongDistance -6.51 ExtraOffset 0
sketch "Sketch16" plane through (0, 0, -6.51) normal (0, 0, 1) x axis (1, 0, 0)
  circle C1 centre (-20.3, -10) radius 0.8
extrude "Extrude16" add sketch "Sketch16" along normal blind 6.46
work_plane "WorkPlane17" AlongDistance -6.51 ExtraOffset 0
sketch "Sketch17" plane through (0, 0, -6.51) normal (0, 0, 1) x axis (1, 0, 0)
  circle C1 centre (-1.7, -12.2) radius 0.8
extrude "Extrude17" add sketch "Sketch17" along normal blind 6.46
work_plane "WorkPlane18" AlongDistance -7.8 ExtraOffset 0
sketch "Sketch18" plane through (0, 0, -7.8) normal (0, 0, 1) x axis (1, 0, 0)
  line L1 (4, -27.6) -> (-4, -27.6)
  line L2 (4, -26.5) -> (4, -27.6)
  line L3 (-4, -26.5) -> (4, -26.5)
  line L4 (-4, -27.6) -> (-4, -26.5)
extrude "Extrude18" cut sketch "Sketch18" along normal blind 0.65
work_plane "WorkPlane19" AlongDistance -6.8 ExtraOffset 0
sketch "Sketch19" plane through (0, 0, -6.8) normal (0, 0, 1) x axis (1, 0, 0)
  circle C1 centre (11, -15.3) radius 10.3
extrude "Extrude19" cut sketch "Sketch19" along normal blind 0.31
work_plane "WorkPlane20" AlongDistance -7.7 ExtraOffset 0
sketch "Sketch20" plane through (0, 0, -7.7) normal (0, 0, 1) x axis (1, 0, 0)
  line L1 (-11.95, -9.65) -> (-15.05, -9.65)
  line L2 (-9.75, -4.35) -> (-9.75, -7.45)
  line L3 (-15.05, -2.15) -> (-11.95, -2.15)
  line L4 (-17.25, -7.45) -> (-17.25, -4.35)
  line L5 (-11.95, -9.05) -> (-15.05, -9.05)
  line L6 (-10.35, -4.35) -> (-10.35, -7.45)
  line L7 (-15.05, -2.75) -> (-11.95, -2.75)
  line L8 (-16.65, -7.45) -> (-16.65, -4.35)
  arc A1 centre (-11.95, -7.45) radius 2.2 clockwise from (-9.75, -7.45) to (-11.95, -9.65)
  arc A2 centre (-11.95, -4.35) radius 2.2 clockwise from (-11.95, -2.15) to (-9.75, -4.35)
  arc A3 centre (-15.05, -4.35) radius 2.2 clockwise from (-17.25, -4.35) to (-15.05, -2.15)
  arc A4 centre (-15.05, -7.45) radius 2.2 clockwise from (-15.05, -9.65) to (-17.25, -7.45)
  arc A5 centre (-11.95, -7.45) radius 1.6 clockwise from (-10.35, -7.45) to (-11.95, -9.05)
  arc A6 centre (-11.95, -4.35) radius 1.6 clockwise from (-11.95, -2.75) to (-10.35, -4.35)
  arc A7 centre (-15.05, -4.35) radius 1.6 clockwise from (-16.65, -4.35) to (-15.05, -2.75)
  arc A8 centre (-15.05, -7.45) radius 1.6 clockwise from (-15.05, -9.05) to (-16.65, -7.45)
extrude "Extrude20" cut sketch "Sketch20" along normal blind 0.3
work_plane "WorkPlane21" AlongDistance -7.7 ExtraOffset 0
sketch "Sketch21" plane through (0, 0, -7.7) normal (0, 0, 1) x axis (1, 0, 0)
  line L1 (-2.95, -9.65) -> (-6.05, -9.65)
  line L2 (-0.75, -4.35) -> (-0.75, -7.45)
  line L3 (-6.05, -2.15) -> (-2.95, -2.15)
  line L4 (-8.25, -7.45) -> (-8.25, -4.35)
  line L5 (-2.95, -9.05) -> (-6.05, -9.05)
  line L6 (-1.35, -4.35) -> (-1.35, -7.45)
  line L7 (-6.05, -2.75) -> (-2.95, -2.75)
  line L8 (-7.65, -7.45) -> (-7.65, -4.35)
  arc A1 centre (-2.95, -7.45) radius 2.2 clockwise from (-0.75, -7.45) to (-2.95, -9.65)
  arc A2 centre (-2.95, -4.35) radius 2.2 clockwise from (-2.95, -2.15) to (-0.75, -4.35)
  arc A3 centre (-6.05, -4.35) radius 2.2 clockwise from (-8.25, -4.35) to (-6.05, -2.15)
  arc A4 centre (-6.05, -7.45) radius 2.2 clockwise from (-6.05, -9.65) to (-8.25, -7.45)
  arc A5 centre (-2.95, -7.45) radius 1.6 clockwise from (-1.35, -7.45) to (-2.95, -9.05)
  arc A6 centre (-2.95, -4.35) radius 1.6 clockwise from (-2.95, -2.75) to (-1.35, -4.35)
  arc A7 centre (-6.05, -4.35) radius 1.6 clockwise from (-7.65, -4.35) to (-6.05, -2.75)
  arc A8 centre (-6.05, -7.45) radius 1.6 clockwise from (-6.05, -9.05) to (-7.65, -7.45)
extrude "Extrude21" cut sketch "Sketch21" along normal blind 0.3
work_plane "WorkPlane22" AlongDistance -7.7 ExtraOffset 0
sketch "Sketch22" plane through (0, 0, -7.7) normal (0, 0, 1) x axis (1, 0, 0)
  line L1 (-5.7, -7.9) -> (-6.5, -7.9)
  line L2 (-5.7, -7.1) -> (-5.7, -7.9)
  line L3 (-6.5, -7.1) -> (-5.7, -7.1)
  line L4 (-6.5, -7.9) -> (-6.5, -7.1)
  line L5 (-4.1, -7.9) -> (-4.9, -7.9)
  line L6 (-4.1, -7.1) -> (-4.1, -7.9)
  line L7 (-4.9, -7.1) -> (-4.1, -7.1)
  line L8 (-4.9, -7.9) -> (-4.9, -7.1)
  line L9 (-2.5, -7.9) -> (-3.3, -7.9)
  line L10 (-2.5, -7.1) -> (-2.5, -7.9)
  line L11 (-3.3, -7.1) -> (-2.5, -7.1)
  line L12 (-3.3, -7.9) -> (-3.3, -7.1)
  line L13 (-5.7, -6.3) -> (-6.5, -6.3)
  line L14 (-5.7, -5.5) -> (-5.7, -6.3)
  line L15 (-6.5, -5.5) -> (-5.7, -5.5)
  line L16 (-6.5, -6.3) -> (-6.5, -5.5)
  line L17 (-4.1, -6.3) -> (-4.9, -6.3)
  line L18 (-4.1, -5.5) -> (-4.1, -6.3)
  line L19 (-4.9, -5.5) -> (-4.1, -5.5)
  line L20 (-4.9, -6.3) -> (-4.9, -5.5)
  line L21 (-2.5, -6.3) -> (-3.3, -6.3)
  line L22 (-2.5, -5.5) -> (-2.5, -6.3)
  line L23 (-3.3, -5.5) -> (-2.5, -5.5)
  line L24 (-3.3, -6.3) -> (-3.3, -5.5)
  line L25 (-5.7, -4.7) -> (-6.5, -4.7)
  line L26 (-5.7, -3.9) -> (-5.7, -4.7)
  line L27 (-6.5, -3.9) -> (-5.7, -3.9)
  line L28 (-6.5, -4.7) -> (-6.5, -3.9)
  line L29 (-4.1, -4.7) -> (-4.9, -4.7)
  line L30 (-4.1, -3.9) -> (-4.1, -4.7)
  line L31 (-4.9, -3.9) -> (-4.1, -3.9)
  line L32 (-4.9, -4.7) -> (-4.9, -3.9)
  line L33 (-2.5, -4.7) -> (-3.3, -4.7)
  line L34 (-2.5, -3.9) -> (-2.5, -4.7)
  line L35 (-3.3, -3.9) -> (-2.5, -3.9)
  line L36 (-3.3, -4.7) -> (-3.3, -3.9)
extrude "Extrude22" cut sketch "Sketch22" along normal blind 0.3
work_plane "WorkPlane23" AlongDistance -7.7 ExtraOffset 0
sketch "Sketch23" plane through (0, 0, -7.7) normal (0, 0, 1) x axis (1, 0, 0)
  line L1 (6.05, -9.65) -> (2.95, -9.65)
  line L2 (8.25, -4.35) -> (8.25, -7.45)
  line L3 (2.95, -2.15) -> (6.05, -2.15)
  line L4 (0.75, -7.45) -> (0.75, -4.35)
  line L5 (6.05, -9.05) -> (2.95, -9.05)
  line L6 (7.65, -4.35) -> (7.65, -7.45)
  line L7 (2.95, -2.75) -> (6.05, -2.75)
  line L8 (1.35, -7.45) -> (1.35, -4.35)
  arc A1 centre (6.05, -7.45) radius 2.2 clockwise from (8.25, -7.45) to (6.05, -9.65)
  arc A2 centre (6.05, -4.35) radius 2.2 clockwise from (6.05, -2.15) to (8.25, -4.35)
  arc A3 centre (2.95, -4.35) radius 2.2 clockwise from (0.75, -4.35) to (2.95, -2.15)
  arc A4 centre (2.95, -7.45) radius 2.2 clockwise from (2.95, -9.65) to (0.75, -7.45)
  arc A5 centre (6.05, -7.45) radius 1.6 clockwise from (7.65, -7.45) to (6.05, -9.05)
  arc A6 centre (6.05, -4.35) radius 1.6 clockwise from (6.05, -2.75) to (7.65, -4.35)
  arc A7 centre (2.95, -4.35) radius 1.6 clockwise from (1.35, -4.35) to (2.95, -2.75)
  arc A8 centre (2.95, -7.45) radius 1.6 clockwise from (2.95, -9.05) to (1.35, -7.45)
extrude "Extrude23" cut sketch "Sketch23" along normal blind 0.3
work_plane "WorkPlane24" AlongDistance -7.7 ExtraOffset 0
sketch "Sketch24" plane through (0, 0, -7.7) normal (0, 0, 1) x axis (1, 0, 0)
  line L1 (4.375, -8.325) -> (3.775, -8.325)
  line L2 (4.375, -7.725) -> (4.375, -8.325)
  line L3 (3.775, -7.725) -> (4.375, -7.725)
  line L4 (3.775, -8.325) -> (3.775, -7.725)
  line L5 (6.075, -8.325) -> (5.475, -8.325)
  line L6 (6.075, -7.725) -> (6.075, -8.325)
  line L7 (5.475, -7.725) -> (6.075, -7.725)
  line L8 (5.475, -8.325) -> (5.475, -7.725)
  line L9 (3.525, -7.475) -> (2.925, -7.475)
  line L10 (3.525, -6.875) -> (3.525, -7.475)
  line L11 (2.925, -6.875) -> (3.525, -6.875)
  line L12 (2.925, -7.475) -> (2.925, -6.875)
  line L13 (5.225, -7.475) -> (4.625, -7.475)
  line L14 (5.225, -6.875) -> (5.225, -7.475)
  line L15 (4.625, -6.875) -> (5.225, -6.875)
  line L16 (4.625, -7.475) -> (4.625, -6.875)
  line L17 (6.925, -7.475) -> (6.325, -7.475)
  line L18 (6.925, -6.875) -> (6.925, -7.475)
  line L19 (6.325, -6.875) -> (6.925, -6.875)
  line L20 (6.325, -7.475) -> (6.325, -6.875)
  line L21 (2.675, -6.625) -> (2.075, -6.625)
  line L22 (2.675, -6.025) -> (2.675, -6.625)
  line L23 (2.075, -6.025) -> (2.675, -6.025)
  line L24 (2.075, -6.625) -> (2.075, -6.025)
  line L25 (4.375, -6.625) -> (3.775, -6.625)
  line L26 (4.375, -6.025) -> (4.375, -6.625)
  line L27 (3.775, -6.025) -> (4.375, -6.025)
  line L28 (3.775, -6.625) -> (3.775, -6.025)
  line L29 (6.075, -6.625) -> (5.475, -6.625)
  line L30 (6.075, -6.025) -> (6.075, -6.625)
  line L31 (5.475, -6.025) -> (6.075, -6.025)
  line L32 (5.475, -6.625) -> (5.475, -6.025)
  line L33 (3.525, -5.775) -> (2.925, -5.775)
  line L34 (3.525, -5.175) -> (3.525, -5.775)
  line L35 (2.925, -5.175) -> (3.525, -5.175)
  line L36 (2.925, -5.775) -> (2.925, -5.175)
  line L37 (5.225, -5.775) -> (4.625, -5.775)
  line L38 (5.225, -5.175) -> (5.225, -5.775)
  line L39 (4.625, -5.175) -> (5.225, -5.175)
  line L40 (4.625, -5.775) -> (4.625, -5.175)
  line L41 (6.925, -5.775) -> (6.325, -5.775)
  line L42 (6.925, -5.175) -> (6.925, -5.775)
  line L43 (6.325, -5.175) -> (6.925, -5.175)
  line L44 (6.325, -5.775) -> (6.325, -5.175)
  line L45 (2.675, -4.925) -> (2.075, -4.925)
  line L46 (2.675, -4.325) -> (2.675, -4.925)
  line L47 (2.075, -4.325) -> (2.675, -4.325)
  line L48 (2.075, -4.925) -> (2.075, -4.325)
  line L49 (4.375, -4.925) -> (3.775, -4.925)
  line L50 (4.375, -4.325) -> (4.375, -4.925)
  line L51 (3.775, -4.325) -> (4.375, -4.325)
  line L52 (3.775, -4.925) -> (3.775, -4.325)
  line L53 (6.075, -4.925) -> (5.475, -4.925)
  line L54 (6.075, -4.325) -> (6.075, -4.925)
  line L55 (5.475, -4.325) -> (6.075, -4.325)
  line L56 (5.475, -4.925) -> (5.475, -4.325)
  line L57 (3.525, -4.075) -> (2.925, -4.075)
  line L58 (3.525, -3.475) -> (3.525, -4.075)
  line L59 (2.925, -3.475) -> (3.525, -3.475)
  line L60 (2.925, -4.075) -> (2.925, -3.475)
  line L61 (5.225, -4.075) -> (4.625, -4.075)
  line L62 (5.225, -3.475) -> (5.225, -4.075)
  line L63 (4.625, -3.475) -> (5.225, -3.475)
  line L64 (4.625, -4.075) -> (4.625, -3.475)
extrude "Extrude24" cut sketch "Sketch24" along normal blind 0.3
work_plane "WorkPlane25" AlongDistance -7.7 ExtraOffset 0
sketch "Sketch25" plane through (0, 0, -7.7) normal (0, 0, 1) x axis (1, 0, 0)
  line L1 (15.05, -9.65) -> (11.95, -9.65)
  line L2 (17.25, -4.35) -> (17.25, -7.45)
  line L3 (11.95, -2.15) -> (15.05, -2.15)
  line L4 (9.75, -7.45) -> (9.75, -4.35)
  arc A1 centre (15.05, -7.45) radius 2.2 clockwise from (17.25, -7.45) to (15.05, -9.65)
  arc A2 centre (15.05, -4.35) radius 2.2 clockwise from (15.05, -2.15) to (17.25, -4.35)
  arc A3 centre (11.95, -4.35) radius 2.2 clockwise from (9.75, -4.35) to (11.95, -2.15)
  arc A4 centre (11.95, -7.45) radius 2.2 clockwise from (11.95, -9.65) to (9.75, -7.45)
extrude "Extrude25" cut sketch "Sketch25" along normal blind 0.3
work_plane "WorkPlane1" AlongDistance -5.8 ExtraOffset 0
sketch "Sketch1" plane through (0, 0, -5.8) normal (0, 0, 1) x axis (1, 0, 0)
  line L1 (8.4, -6.9) -> (-21.6, -6.9)
  line L2 (8.4, 13.1) -> (8.4, -6.9)
  line L3 (-21.6, 13.1) -> (8.4, 13.1)
  line L4 (-21.6, -6.9) -> (-21.6, 13.1)
extrude "Extrude1" new body sketch "Sketch1" along normal blind 5 bodies "LiPo 30x20x5"
work_plane "WorkPlane2" AlongDistance -6.5 ExtraOffset 0
sketch "Sketch2" plane through (0, 0, -6.5) normal (0, 0, 1) x axis (1, 0, 0)
  circle C1 centre (15.5, 4) radius 5
extrude "Extrude2" new body sketch "Sketch2" along normal blind 2.7 bodies "Vibration motor 10x2.7"
work_plane "WorkPlane3" AlongDistance -1.3 ExtraOffset 0
sketch "Sketch3" plane through (0, 0, -1.3) normal (0, 0, 1) x axis (1, 0, 0)
  line L1 (21.6, -24.9) -> (0.6, -24.9)
  line L2 (21.6, -7.1) -> (21.6, -24.9)
  line L3 (0.6, -7.1) -> (21.6, -7.1)
  line L4 (0.6, -24.9) -> (0.6, -7.1)
extrude "Extrude3" new body sketch "Sketch3" along normal blind 1 bodies "XIAO ESP32-S3 (upside down)"
work_plane "WorkPlane4" AlongDistance -4.5 ExtraOffset 0
sketch "Sketch4" plane through (0, 0, -4.5) normal (0, 0, 1) x axis (1, 0, 0)
  line L1 (22, -20.45) -> (14.6, -20.45)
  line L2 (22, -11.55) -> (22, -20.45)
  line L3 (14.6, -11.55) -> (22, -11.55)
  line L4 (14.6, -20.45) -> (14.6, -11.55)
extrude "Extrude4" add sketch "Sketch4" along normal blind 3.2
work_plane "WorkPlane5" AlongDistance -3.8 ExtraOffset 0
sketch "Sketch5" plane through (0, 0, -3.8) normal (0, 0, 1) x axis (1, 0, 0)
  line L1 (14.6, -23.9) -> (1.6, -23.9)
  line L2 (14.6, -8.1) -> (14.6, -23.9)
  line L3 (1.6, -8.1) -> (14.6, -8.1)
  line L4 (1.6, -23.9) -> (1.6, -8.1)
extrude "Extrude5" add sketch "Sketch5" along normal blind 2.5
work_plane "WorkPlane6" AlongDistance -6.5 ExtraOffset 0
sketch "Sketch6" plane through (0, 0, -6.5) normal (0, 0, 1) x axis (1, 0, 0)
  line L1 (-4, -24.9) -> (-18, -24.9)
  line L2 (-4, -10.9) -> (-4, -24.9)
  line L3 (-18, -10.9) -> (-4, -10.9)
  line L4 (-18, -24.9) -> (-18, -10.9)
extrude "Extrude6" new body sketch "Sketch6" along normal blind 6.2 bodies "DS3231 14x14 (no header)"
work_plane "WorkPlane7" AlongDistance -6.8 ExtraOffset 0
sketch "Sketch7" plane through (0, 0, -6.8) normal (0, 0, 1) x axis (1, 0, 0)
  circle C1 centre (11, -15.3) radius 10
extrude "Extrude7" new body sketch "Sketch7" along normal blind 0.5 bodies "Piezo disc 20mm"
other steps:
create_component "CreateComponent1"
create_component "CreateComponent59"
create_component "CreateComponent60"
create_component "CreateComponent61"
named bodies: "Shell", "Back", "LiPo 30x20x5", "Vibration motor 10x2.7", "XIAO ESP32-S3 (upside down)", "DS3231 14x14 (no header)", "Piezo disc 20mm"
